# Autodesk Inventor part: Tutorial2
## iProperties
Shininess: 77.0
Length Units: 11269
Angle Units: 11279
Time Units: 11290
Mass Units: 11283
Length Display Precision: 3
Angle Display Precision: 2
Created: 2001-12
Part Number: Tutorial2
Document SubType Name: Modeling
Designer: Renu Muthoo
Density: 1 g/cm^3
Density: 0.0
Volumn: 0.0
Area: 0.0
PropertySet Name: Model Information
Control State: 0
Master: False
Checked Out: False
Author: Renu Muthoo
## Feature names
1. Extrusion1
2. Extrusion2
3. Extrusion3
4. Extrusion4
5. Extrusion5
6. Mirror2
7. Hole3
